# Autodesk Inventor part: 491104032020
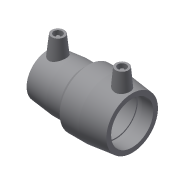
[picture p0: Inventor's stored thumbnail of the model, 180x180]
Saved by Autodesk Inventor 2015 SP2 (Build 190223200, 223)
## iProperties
Created: 2017-06
Part Number: 491104032020
Material: Generic
Description: PLASSON REDUCING COUPLER 32-20
Document SubType Name: Modeling
Designer: KIM
Mass: 54.8237 g
Surface Area: 155.252 cm^2
Volume: 54.8237 cm^3
Density: 1 g/cm^3
Appearance: Default
Author: KIM
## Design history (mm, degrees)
derived "491104.ipt"
feature "Solid1::491104.ipt"
tag "TaggingFeature1"
body "Solid1"
other parameters: "L_" = 81, "L_2" = 35, "D_1" = 32, "A_1" = 37, "d_2" = 12, "d_" = 32, "A_" = 43, "D_" = 45, "d0" = 81, "d2" = 32, "d3" = 35, "d4" = 21, "d5" = 28.8, "d8" = 168 deg, "d10" = 14, "d11" = 4.66667, "d13" = 81, "d14" = 17.6296, "d15" = 35, "d19" = 1.75, "d20" = 168 deg, "d22" = 108.92847, "d25" = 135 deg, "d29" = 37, "d30" = 15, "d31" = 28.35, "d34" = 6 deg, "d35" = 15, "d38" = 26, "d39" = 5 deg, "d41" = 4, "d42" = 14, "d43" = 0, "d45" = 4, "d46" = 14, "d47" = 0, "d48" = 32, "d49" = 32, "d50" = 45, "d52" = 18, "d53" = 16, "d54" = 5.33333, "d55" = 168 deg, "d56" = 24, "d58" = 40.5, "d59" = 1.75, "d60" = 135 deg, "d61" = 43, "d62" = 15, "d64" = 4, "d66" = 5 deg, "d67" = 14, "d68" = 0, "d69" = 28.35, "d70" = 32, "d71" = 45, "d73" = 42.3, "d76" = 1.75, "d77" = 168 deg, "d78" = 32, "d79" = 1.75, "d81" = 18, "d82" = 30.08, "d83" = 120 deg, "d88" = 15, "d89" = 25.4, "d90" = 5 deg, "d92" = 4, "d93" = 14, "d94" = 0, "d95" = 3, "d96" = 0, "d97" = 3, "d98" = 0, "d99" = 10.15, "d100" = 2.5375, "d101" = 29.1776, "d102" = 20 deg, "d103" = 11.6, "d104" = 2.9, "d105" = 41.031, "d106" = 3.60705, "d107" = 3, "d108" = 0, "d109" = 3, "d110" = 0
